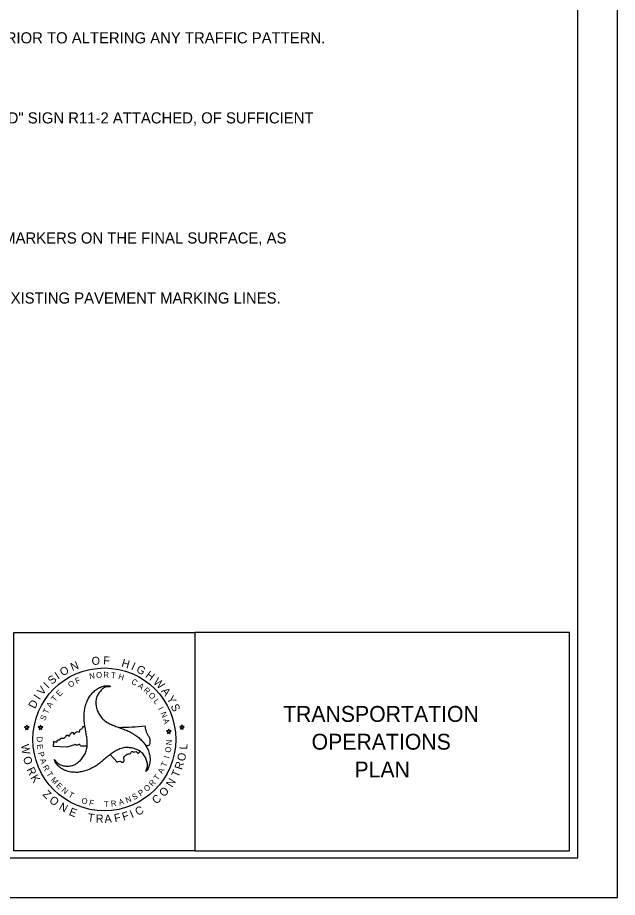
# Model space of a CAD drawing. Extents: x -38542 to 45858, y -25814 to 29186.
# Drawn here: x 1478 to 1856, y -628 to -74 of the extents above; entities that cross this region are included whole.
import ezdxf

# ---------------------------------------------------------------- set-up
doc = ezdxf.new("R2010")
doc.units = 0
for name, color, linetype in [('DEV TYPE 3 BARRICADE WITH R11-2 M4-10R CELL', 7, 'Continuous'), ('Exist Road Non-System Type 51 Label', 7, 'Continuous'), ('Sheet Plan CELL', 7, 'Continuous'), ('Sheet Plot Border Outside CELL', 7, 'Continuous'), ('WZ RC1000 CELL', 7, 'Continuous'), ('WZ RCANL CELL', 7, 'Continuous')]:
    doc.layers.add(name, color=color, linetype=linetype)

msp = doc.modelspace()

# ---------------------------------------------------------------- linework, layer by layer
at = {"layer": 'DEV TYPE 3 BARRICADE WITH R11-2 M4-10R CELL'}
msp.add_circle((1532.81, -528.89), 44.97, dxfattribs=at)
at = {"layer": 'Exist Road Non-System Type 51 Label'}
msp.add_lwpolyline([(1830.96, 446.64), (330.96, 446.64), (330.96, -603.36), (1830.96, -603.36)], close=True, dxfattribs=at)
at = {"layer": 'Sheet Plot Border Outside CELL'}
msp.add_lwpolyline([(167.97, -628.36), (1855.96, -628.36), (1855.96, 471.64), (167.97, 471.64)], close=True, dxfattribs=at)
at = {"layer": 'WZ RC1000 CELL'}
for points in [[(1475.81, -461.59), (1589.81, -461.59), (1589.81, -599.09), (1475.81, -599.09)], [(1825.81, -461.59), (1589.81, -461.59), (1589.81, -599.09), (1825.81, -599.09)]]:
    msp.add_lwpolyline(points, close=True, dxfattribs=at)
at = {"layer": 'WZ RCANL CELL'}
for p, q in [((1483.95, -519.92), (1483.63, -520.93)), ((1484.31, -520.93), (1483.95, -519.92)), ((1492.63, -519.94), (1492.3, -520.94)), ((1492.99, -520.94), (1492.63, -519.94)), ((1581.67, -519.79), (1581.35, -520.79)), ((1582.03, -520.79), (1581.67, -519.79)), ((1482.54, -520.93), (1483.42, -521.57)), ((1483.63, -520.93), (1482.54, -520.93)), ((1483.42, -521.57), (1483.1, -522.61)), ((1483.1, -522.61), (1483.95, -521.97)), ((1483.95, -521.97), (1484.83, -522.61)), ((1483.95, -521.97), (1484.83, -522.61)), ((1485.39, -520.93), (1484.31, -520.93)), ((1484.51, -521.57), (1485.39, -520.93)), ((1484.51, -521.57), (1485.39, -520.93)), ((1484.83, -522.61), (1484.51, -521.57)), ((1484.83, -522.61), (1484.51, -521.57)), ((1492.3, -520.94), (1491.22, -520.94)), ((1491.22, -520.94), (1492.1, -521.58)), ((1492.1, -521.58), (1491.78, -522.63)), ((1491.78, -522.63), (1492.63, -521.99)), ((1492.63, -521.99), (1493.51, -522.63)), ((1494.07, -520.94), (1492.99, -520.94)), ((1493.19, -521.58), (1494.07, -520.94)), ((1493.51, -522.63), (1493.19, -521.58)), ((1573.07, -523.43), (1571.99, -523.43)), ((1571.99, -523.43), (1572.87, -524.07)), ((1572.87, -524.07), (1572.55, -525.12)), ((1572.55, -525.12), (1573.39, -524.48)), ((1573.39, -522.43), (1573.07, -523.43)), ((1573.76, -523.43), (1573.39, -522.43)), ((1573.39, -524.48), (1574.28, -525.12)), ((1574.84, -523.43), (1573.76, -523.43)), ((1573.95, -524.07), (1574.84, -523.43)), ((1574.28, -525.12), (1573.95, -524.07)), ((1581.35, -520.79), (1580.26, -520.79)), ((1580.26, -520.79), (1581.15, -521.43)), ((1581.15, -521.43), (1580.83, -522.47)), ((1580.83, -522.47), (1581.67, -521.83)), ((1581.67, -521.83), (1582.56, -522.47)), ((1583.12, -520.79), (1582.03, -520.79)), ((1582.23, -521.43), (1583.12, -520.79)), ((1582.56, -522.47), (1582.23, -521.43)), ((1500.87, -533.37), (1500.95, -530.72)), ((1509.26, -533.68), (1500.87, -533.37)), ((1514.06, -532.27), (1509.26, -533.68)), ((1517.77, -532.83), (1521.98, -532.87)), ((1536.51, -538.45), (1540.82, -543.12))]:
    msp.add_line(p, q, dxfattribs=at)
for start, end in [(271.2035, 275.3236), (265.6785, 265.9762)]:
    msp.add_arc((1536.9, -288.19), 233.19, start, end, dxfattribs=at)
for points in [[(1501.28, -541.48), (1503.02, -543.5), (1505.2, -544.89), (1507.7, -545.54), (1510.51, -545.7), (1513.39, -545.03), (1515.29, -544.06), (1516.1, -543.42), (1517.49, -542.32), (1518.49, -541.24), (1520.15, -538.88), (1521.44, -536.09), (1521.98, -532.89), (1522, -532.62), (1521.98, -529.62), (1521.57, -526.58), (1521.14, -523.66), (1520.61, -520.63), (1520.13, -517.62), (1520.07, -514.69), (1520.26, -511.34), (1520.74, -508.47), (1521.68, -505.51), (1522.19, -504.12), (1522.89, -502.99), (1524.63, -500.33), (1526.92, -498.19), (1528.42, -497.06), (1529.84, -496.3), (1530.08, -496.17), (1532.93, -495.26), (1535.72, -495.15), (1536.66, -495.39)], [(1536.74, -495.31), (1536.66, -495.39), (1534.08, -495.87), (1531.75, -497.08), (1529.95, -498.91), (1528.42, -501.25), (1527.56, -504.09), (1527.43, -506.21), (1527.61, -507.23), (1527.86, -509), (1528.26, -510.4), (1529.52, -513), (1531.26, -515.53), (1533.79, -517.59), (1534, -517.75), (1536.58, -519.23), (1539.45, -520.41), (1542.19, -521.49), (1545.06, -522.53), (1547.91, -523.66), (1550.48, -525.06), (1553.31, -526.88), (1555.53, -528.73), (1557.63, -531.01), (1558.59, -532.17), (1559.21, -533.35), (1560.66, -536.17), (1561.36, -539.23), (1561.6, -541.11), (1561.55, -542.72), (1561.55, -542.99), (1560.87, -545.91), (1559.56, -548.38), (1558.91, -549.05)], [(1558.84, -532.6), (1561.31, -532.3), (1561.68, -530.35), (1561.7, -528.71), (1560.69, -526.82), (1559.16, -523.34), (1558.54, -520.37)], [(1500.95, -530.72), (1500.87, -530.46), (1501.32, -530.18), (1502.56, -530.69), (1503.18, -530.15), (1503.16, -529.61), (1503.67, -529.08), (1504.51, -529.25), (1505.28, -528.29), (1505.98, -528.09), (1507.48, -528.09), (1509.26, -526.31), (1509.99, -526.2), (1510.19, -526.68), (1510.64, -526.76), (1511.43, -525.29), (1511.63, -525.09), (1512.99, -524.53), (1513.36, -524.81), (1513.47, -525.46), (1513.67, -525.57), (1514.12, -525.26), (1514.74, -524.47), (1515.87, -523.88), (1517.17, -524.05), (1517.4, -522.97), (1518.92, -521.96), (1519.23, -521.34), (1519.32, -520.71)], [(1558.91, -549.05), (1559.77, -546.59), (1559.91, -543.98), (1559.21, -541.48), (1557.95, -538.99), (1555.93, -536.84), (1554.16, -535.66), (1553.17, -535.31), (1551.56, -534.61), (1550.08, -534.29), (1547.24, -534.05), (1544.15, -534.32), (1541.12, -535.47), (1540.87, -535.58), (1538.3, -537.11), (1535.85, -538.96), (1533.52, -540.78), (1531.19, -542.77), (1528.79, -544.71), (1526.3, -546.21), (1523.29, -547.74), (1520.58, -548.73), (1517.58, -549.4), (1516.07, -549.67), (1514.76, -549.62), (1511.61, -549.46), (1508.58, -548.55), (1506.86, -547.82), (1505.5, -546.93), (1505.25, -546.8), (1503.05, -544.79), (1501.58, -542.42), (1501.28, -541.48)], [(1517.77, -532.83), (1517.42, -532.19), (1516.75, -531.99), (1515.82, -532.47), (1515.14, -532.44), (1514.37, -531.88), (1514.06, -532.27)], [(1540.82, -543.12), (1542.52, -542.61), (1543.93, -543.15), (1544.61, -543.26), (1545.18, -542.84), (1545, -540.72), (1545.49, -539.73), (1547.78, -538.03), (1549.19, -537.72), (1550.23, -536.42), (1550.66, -536.45), (1551.3, -536.82), (1552.75, -536.54), (1553.9, -537.47), (1554.58, -537.41), (1555.13, -536.35)]]:
    msp.add_spline(points, degree=3, dxfattribs=at)

# ---------------------------------------------------------------- texts
at = {"layer": 'DEV TYPE 3 BARRICADE WITH R11-2 M4-10R CELL'}
for s, height, rotation, p in [('T', 3.63, 353.7884, (1536.84, -490.18)), ('W', 5.04, 278.15, (1480.33, -532.26)), ('L', 5.04, 87.429, (1585.01, -535.34)), ('O', 5.04, 287.1147, (1481.49, -540.4)), ('O', 5.04, 78.9896, (1583.5, -542.93)), ('R', 5.04, 295.5541, (1483.74, -547.8)), ('T', 5.04, 66.881, (1579.43, -553.25)), ('R', 5.04, 72.7519, (1581.67, -548.35)), ('K', 5.04, 301.7918, (1486.09, -553.02)), ('N', 5.04, 58.892, (1575.59, -559.49)), ('O', 5.04, 50.4526, (1570.63, -565.43)), ('Z', 5.04, 316.1688, (1493.54, -563.87)), ('O', 5.04, 322.5233, (1497.66, -568)), ('C', 5.04, 43.0807, (1565.63, -569.98)), ('N', 5.04, 330.9626, (1503.78, -572.74)), ('E', 5.04, 338.9517, (1510.15, -576.35)), ('T', 5.04, 352.6948, (1522.08, -580.37)), ('F', 5.04, 11.7751, (1539.5, -581.05)), ('F', 5.04, 17.7627, (1544.9, -580.07)), ('I', 5.04, 23.7503, (1550.18, -578.53)), ('C', 5.04, 28.0033, (1553.81, -577.11)), ('R', 5.04, 358.5656, (1527.4, -581.2)), ('A', 5.04, 4.8034, (1533.12, -581.48))]:
    msp.add_text(s, height=height, rotation=rotation, dxfattribs=at).set_placement(p)
at = {"layer": 'Exist Road Non-System Type 51 Label'}
for s, p in [('TRANSPORTATION', (1645.36, -517.84)), ('OPERATIONS', (1663.36, -535.34)), ('PLAN', (1690.36, -552.84))]:
    msp.add_text(s, height=10, dxfattribs=at).set_placement(p)
at = {"layer": 'Sheet Plan CELL'}
for s, p in [('E) ENSURE ALL NECESSARY SIGNING IS IN PLACE PRIOR TO ALTERING ANY TRAFFIC PATTERN.', (1232.45, -90.69)), ('F) PLACE TYPE III BARRICADES, WITH "ROAD CLOSED" SIGN R11-2 ATTACHED, OF SUFFICIENT', (1232.45, -141.09)), ('G) INSTALL PAVEMENT MARKINGS AND PAVEMENT MARKERS ON THE FINAL SURFACE, AS ', (1232.45, -216.69)), ('H) THE PROPOSED PAVEMENT MARKING LINES TO EXISTING PAVEMENT MARKING LINES.', (1232.45, -254.49))]:
    msp.add_text(s, height=7, rotation=0, dxfattribs=at).set_placement(p)
at = {"layer": 'WZ RCANL CELL'}
for s, height, rotation, p in [('N', 5.04, 21.5861, (1512.67, -485.89)), ('O', 5.04, 5.7649, (1525.07, -482.16)), ('F', 5.04, 357.2575, (1532.03, -481.6)), ('H', 5.04, 343.454, (1543.26, -482.89)), ('I', 5.04, 335.804, (1549.25, -484.76)), ('I', 5.04, 34.3808, (1503.69, -491.29)), ('O', 5.04, 30.0935, (1506.56, -489.26)), ('N', 3.63, 9.0227, (1523.59, -490.94)), ('O', 3.63, 3.9446, (1527.74, -490.22)), ('R', 3.63, 358.8665, (1532.21, -489.95)), ('G', 5.04, 331.5167, (1552.48, -486.15)), ('H', 5.04, 323.4632, (1558.24, -489.4)), ('I', 5.04, 44.8722, (1497.36, -497.13)), ('S', 5.04, 40.5848, (1499.82, -494.6)), ('O', 3.63, 29.335, (1511.16, -496.41)), ('F', 3.63, 24.2569, (1515.37, -494.06)), ('H', 3.63, 343.6322, (1541.29, -490.81)), ('C', 3.63, 333.4761, (1549.52, -493.73)), ('W', 5.04, 315.8133, (1563.23, -493.2)), ('V', 5.04, 51.5806, (1493.92, -501.42)), ('E', 3.63, 44.5692, (1504.55, -502.1)), ('A', 3.63, 323.3199, (1553.62, -495.86)), ('R', 3.63, 318.2418, (1557.12, -498.41)), ('A', 5.04, 306.7762, (1568.41, -498.5)), ('I', 5.04, 55.8679, (1491.99, -504.37)), ('T', 3.63, 49.6473, (1501.69, -505.41)), ('O', 3.63, 313.1637, (1560.32, -501.32)), ('L', 3.63, 308.0856, (1563.54, -505)), ('Y', 5.04, 299.7484, (1571.83, -503.15)), ('D', 5.04, 63.459, (1489.14, -509.91)), ('T', 3.63, 64.8816, (1497.19, -513.18)), ('A', 3.63, 59.8035, (1499.13, -509.39)), ('I', 3.63, 297.9295, (1566.59, -509.5)), ('S', 5.04, 293.2249, (1574.47, -507.8)), ('S', 3.63, 69.9597, (1495.6, -517.33)), ('N', 3.63, 292.8514, (1568.1, -512.41)), ('A', 3.63, 287.7733, (1569.7, -516.46)), ('D', 3.63, 270.272, (1490.26, -527.18)), ('N', 3.63, 87.733, (1575.26, -532.55)), ('E', 3.63, 275.3501, (1490.38, -532.04)), ('P', 3.63, 285.5063, (1490.98, -537.25)), ('O', 3.63, 82.9269, (1574.63, -537.41)), ('A', 3.63, 290.5843, (1492.18, -541.71)), ('T', 3.63, 67.6926, (1571.55, -546.56)), ('I', 3.63, 72.7707, (1573.55, -541.17)), ('R', 3.63, 295.6624, (1493.85, -546.04)), ('A', 3.63, 62.6145, (1569.32, -550.91)), ('T', 3.63, 300.7405, (1496.14, -550.45)), ('M', 3.63, 310.8967, (1498.75, -554.54)), ('T', 3.63, 52.4584, (1566.37, -555.05)), ('E', 3.63, 315.9748, (1502.09, -558.36)), ('N', 3.63, 321.0529, (1505.51, -561.52)), ('O', 3.63, 42.3022, (1559.59, -562.05)), ('R', 3.63, 47.3803, (1563.11, -558.79)), ('T', 3.63, 331.209, (1509.76, -564.76)), ('N', 3.63, 21.9899, (1546.97, -569.05)), ('S', 3.63, 27.068, (1551.38, -567.18)), ('P', 3.63, 32.146, (1555.51, -564.87)), ('O', 3.63, 341.3652, (1517.97, -568.78)), ('F', 3.63, 346.4433, (1522.89, -570.26)), ('T', 3.63, 1.6775, (1532.65, -571.45)), ('R', 3.63, 6.7556, (1537.14, -571.21)), ('A', 3.63, 16.9118, (1542.39, -570.44))]:
    msp.add_text(s, height=height, rotation=rotation, dxfattribs=at).set_placement(p)

doc.saveas('drawing.dxf')
